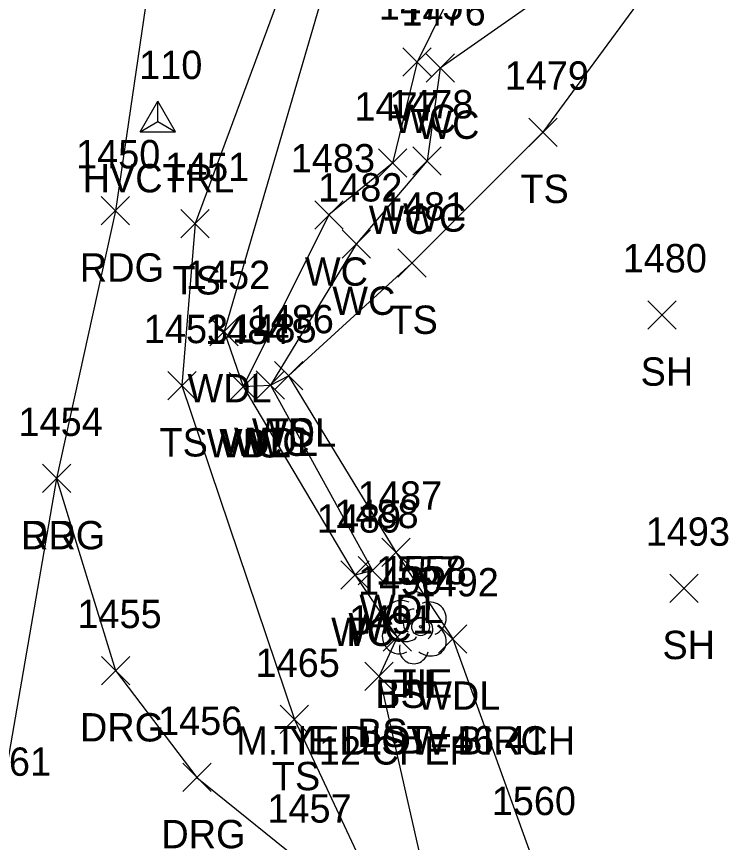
# Model space of a CAD drawing. Extents: x 1678553 to 1680768, y 787260 to 792325.
# Drawn here: x 1678687.1 to 1678737.4, y 787425.2 to 787483.5 of the extents above; entities that cross this region are included whole.
import ezdxf

# ---------------------------------------------------------------- set-up
doc = ezdxf.new("R2010")
doc.units = 0
for name, color, linetype in [('C_A', 7, 'Continuous'), ('C_C', 7, 'Continuous'), ('C_I', 7, 'Continuous'), ('CBP', 7, 'Continuous'), ('CPSM', 7, 'Continuous'), ('D_A', 7, 'Continuous'), ('D_C', 7, 'Continuous'), ('D_I', 7, 'Continuous'), ('D_TIC', 7, 'Continuous'), ('DCP', 7, 'Continuous'), ('L_A', 7, 'Continuous'), ('L_C', 7, 'Continuous'), ('L_I', 7, 'Continuous'), ('L_TIC', 7, 'Continuous'), ('LAWA', 7, 'Continuous'), ('LAWE', 7, 'Continuous'), ('LELB', 7, 'Continuous'), ('LTD', 7, 'Continuous'), ('P_A', 7, 'Continuous'), ('P_I', 7, 'Continuous'), ('P_TIC', 7, 'Continuous'), ('PEU', 7, 'Continuous'), ('R_A', 7, 'Continuous'), ('R_I', 7, 'Continuous'), ('R_TIC', 7, 'Continuous'), ('RDG', 7, 'Continuous')]:
    doc.layers.add(name, color=color, linetype=linetype)

msp = doc.modelspace()

# ---------------------------------------------------------------- linework, layer by layer
at = {"layer": 'CBP'}
for radius in [0.625, 0.0833]:
    msp.add_circle((1678715.655, 787440.466), radius, dxfattribs=at)
at = {"layer": 'CPSM'}
for p, q in [((1678695.859, 787475.405), (1678697.109, 787477.57)), ((1678698.359, 787475.405), (1678697.109, 787477.57)), ((1678697.109, 787476.127), (1678697.109, 787477.57)), ((1678695.859, 787475.405), (1678697.109, 787476.127)), ((1678697.109, 787476.127), (1678697.109, 787476.127)), ((1678697.109, 787476.127), (1678698.359, 787475.405)), ((1678695.859, 787475.405), (1678698.359, 787475.405))]:
    msp.add_line(p, q, dxfattribs=at)
at = {"layer": 'D_TIC'}
for points in [[(1678710.034, 787443.117), (1678712.034, 787445.117)], [(1678712.034, 787443.117), (1678710.034, 787445.117)], [(1678713.015, 787438.741), (1678715.015, 787440.741)], [(1678715.015, 787438.741), (1678713.015, 787440.741)]]:
    msp.add_lwpolyline(points, dxfattribs=at)
at = {"layer": 'DCP'}
msp.add_lwpolyline([(1678711.034, 787444.117), (1678714.015, 787439.741)], dxfattribs=at)
at = {"layer": 'L_TIC'}
for points in [[(1678714.409, 787479.322), (1678716.409, 787481.322)], [(1678716.409, 787479.322), (1678714.409, 787481.322)], [(1678716.048, 787478.906), (1678718.048, 787480.906)], [(1678718.048, 787478.906), (1678716.048, 787480.906)], [(1678723.288, 787474.377), (1678725.288, 787476.377)], [(1678725.288, 787474.377), (1678723.288, 787476.377)], [(1678723.288, 787474.377), (1678725.288, 787476.377)], [(1678725.288, 787474.377), (1678723.288, 787476.377)], [(1678712.685, 787472.198), (1678714.685, 787474.198)], [(1678714.685, 787472.198), (1678712.685, 787474.198)], [(1678715.12, 787472.35), (1678717.12, 787474.35)], [(1678717.12, 787472.35), (1678715.12, 787474.35)], [(1678708.183, 787468.54), (1678710.183, 787470.54)], [(1678710.183, 787468.54), (1678708.183, 787470.54)], [(1678698.74, 787467.921), (1678700.74, 787469.921)], [(1678700.74, 787467.921), (1678698.74, 787469.921)], [(1678710.115, 787466.484), (1678712.115, 787468.484)], [(1678712.115, 787466.484), (1678710.115, 787468.484)], [(1678714.047, 787465.14), (1678716.047, 787467.14)], [(1678716.047, 787465.14), (1678714.047, 787467.14)], [(1678731.695, 787461.484), (1678733.695, 787463.484)], [(1678733.695, 787461.484), (1678731.695, 787463.484)], [(1678700.786, 787460.308), (1678702.786, 787462.308)], [(1678702.786, 787460.308), (1678700.786, 787462.308)], [(1678705.335, 787457.183), (1678707.335, 787459.183)], [(1678707.335, 787457.183), (1678705.335, 787459.183)], [(1678705.335, 787457.183), (1678707.335, 787459.183)], [(1678707.335, 787457.183), (1678705.335, 787459.183)], [(1678697.818, 787456.487), (1678699.818, 787458.487)], [(1678699.818, 787456.487), (1678697.818, 787458.487)], [(1678702.147, 787456.419), (1678704.147, 787458.419)], [(1678704.147, 787456.419), (1678702.147, 787458.419)], [(1678702.147, 787456.419), (1678704.147, 787458.419)], [(1678704.147, 787456.419), (1678702.147, 787458.419)], [(1678704.06, 787456.531), (1678706.06, 787458.531)], [(1678706.06, 787456.531), (1678704.06, 787458.531)], [(1678704.06, 787456.531), (1678706.06, 787458.531)], [(1678706.06, 787456.531), (1678704.06, 787458.531)], [(1678712.921, 787444.734), (1678714.921, 787446.734)], [(1678714.921, 787444.734), (1678712.921, 787446.734)], [(1678711.259, 787443.43), (1678713.259, 787445.43)], [(1678713.259, 787443.43), (1678711.259, 787445.43)], [(1678710.034, 787443.117), (1678712.034, 787445.117)], [(1678712.034, 787443.117), (1678710.034, 787445.117)], [(1678710.034, 787443.117), (1678712.034, 787445.117)], [(1678712.034, 787443.117), (1678710.034, 787445.117)], [(1678733.235, 787442.186), (1678735.235, 787444.186)], [(1678735.235, 787442.186), (1678733.235, 787444.186)], [(1678713.015, 787438.741), (1678715.015, 787440.741)], [(1678715.015, 787438.741), (1678713.015, 787440.741)], [(1678716.921, 787438.613), (1678718.921, 787440.613)], [(1678718.921, 787438.613), (1678716.921, 787440.613)], [(1678711.733, 787435.979), (1678713.733, 787437.979)], [(1678713.733, 787435.979), (1678711.733, 787437.979)], [(1678705.749, 787432.933), (1678707.749, 787434.933)], [(1678707.749, 787432.933), (1678705.749, 787434.933)]]:
    msp.add_lwpolyline(points, dxfattribs=at)
at = {"layer": 'LAWA'}
msp.add_lwpolyline([(1678709.783, 787516.485), (1678712.28, 787497.217), (1678701.786, 787461.308), (1678703.147, 787457.419), (1678705.06, 787457.531), (1678706.335, 787458.183), (1678713.921, 787445.734), (1678717.921, 787439.613), (1678723.5, 787424.177), (1678713.912, 787402.698), (1678707.751, 787397.775), (1678697.862, 787399.447), (1678688.053, 787395.99), (1678683.78, 787387.208), (1678676.741, 787361.633), (1678672.526, 787349.762), (1678668.76, 787338.441), (1678662.119, 787319.948), (1678654.202, 787273.362)], dxfattribs=at)
at = {"layer": 'LAWE'}
for points in [[(1678722.745, 787512.606), (1678722.195, 787494.059), (1678715.409, 787480.322), (1678713.685, 787473.198), (1678709.183, 787469.54), (1678703.147, 787457.419), (1678711.034, 787444.117)], [(1678731.749, 787490.21), (1678717.048, 787479.906), (1678716.12, 787473.35), (1678711.115, 787467.484), (1678705.06, 787457.531), (1678712.259, 787444.43), (1678711.034, 787444.117)]]:
    msp.add_lwpolyline(points, dxfattribs=at)
at = {"layer": 'LELB'}
for points in [[(1678703.248, 787521.158), (1678708.077, 787504.893), (1678710.048, 787496.734), (1678699.74, 787468.921), (1678698.818, 787457.487), (1678706.749, 787433.933), (1678714.451, 787417.51), (1678705.647, 787404.222), (1678696.305, 787404.911), (1678687.529, 787400.609), (1678678.856, 787394.601), (1678669.013, 787365.188), (1678664.736, 787349.076), (1678657.46, 787321.279), (1678652.337, 787297.827), (1678647.466, 787276.322)], [(1678812.782, 787516.249), (1678783.274, 787510.424), (1678763.1, 787494.005), (1678734.556, 787489.379), (1678724.288, 787475.377)], [(1678724.288, 787475.377), (1678715.047, 787466.14), (1678706.335, 787458.183)], [(1678714.015, 787439.741), (1678712.733, 787436.979), (1678716.977, 787418.322), (1678707.935, 787402.889), (1678697.964, 787402.122), (1678688.053, 787395.99)]]:
    msp.add_lwpolyline(points, dxfattribs=at)
at = {"layer": 'LTD'}
msp.add_line((1678715.192, 787440.452), (1678715.192, 787440.452), dxfattribs=at)
msp.add_line((1678715.192, 787440.452), (1678715.192, 787440.452), dxfattribs=at)
msp.add_arc((1678715.239, 787441.886), 1.047, 335.52715, 180.95627, dxfattribs=at)
for centre, major_axis, ratio, start_param, end_param in [((1678714.401, 787441.118), (1.21, -0.512), 0.895232, 1.570796, 4.712389), ((1678716.234, 787441.035), (-1.141, -0.483), 0.949671, 1.570796, 4.712389), ((1678714.984, 787440.91), (-0.208, -0.792), 0.645439, 3.141593, 6.283185), ((1678714.109, 787439.743), (0.584, -1.042), 0.959034, 3.141593, 6.283185), ((1678715.692, 787440.285), (-0.5, 0.667), 0.989748, 3.141593, 6.283185), ((1678716.193, 787439.618), (-1.09, 0.792), 0.841452, 1.570796, 4.712389), ((1678714.734, 787439.701), (-0.625, -0.083), 0.423636, 0, 3.141593), ((1678715.193, 787438.952), (0.265, 1.061), 0.942809, 1.570796, 4.712389)]:
    msp.add_ellipse(centre, major_axis=major_axis, ratio=ratio, start_param=start_param, end_param=end_param, dxfattribs=at)
at = {"layer": 'P_TIC'}
for points in [[(1678693.118, 787468.827), (1678695.118, 787470.827)], [(1678695.118, 787468.827), (1678693.118, 787470.827)], [(1678688.971, 787449.935), (1678690.971, 787451.935)], [(1678690.971, 787449.935), (1678688.971, 787451.935)]]:
    msp.add_lwpolyline(points, dxfattribs=at)
at = {"layer": 'PEU'}
msp.add_lwpolyline([(1678701.084, 787523.46), (1678699.331, 787512.572), (1678697.82, 787495.037), (1678694.118, 787469.827), (1678689.971, 787450.935), (1678685.799, 787426.952), (1678675.551, 787395.19), (1678665.556, 787365.837), (1678662.398, 787349.046), (1678655.839, 787321.611), (1678650.229, 787298.04), (1678645.331, 787276.771)], dxfattribs=at)
at = {"layer": 'R_TIC'}
for points in [[(1678688.971, 787449.935), (1678690.971, 787451.935)], [(1678690.971, 787449.935), (1678688.971, 787451.935)], [(1678693.128, 787436.374), (1678695.128, 787438.374)], [(1678695.128, 787436.374), (1678693.128, 787438.374)], [(1678698.872, 787428.836), (1678700.872, 787430.836)], [(1678700.872, 787428.836), (1678698.872, 787430.836)]]:
    msp.add_lwpolyline(points, dxfattribs=at)
at = {"layer": 'RDG'}
msp.add_lwpolyline([(1678689.971, 787450.935), (1678694.128, 787437.374), (1678699.872, 787429.836), (1678707.534, 787423.647), (1678704.059, 787407.868), (1678691.023, 787410.562), (1678683.252, 787407.317), (1678675.551, 787395.19)], dxfattribs=at)

# ---------------------------------------------------------------- texts
at = {"layer": 'C_A'}
for s, p in [('HVCTRL', (1678691.802, 787471.127)), ('TIE', (1678713.734, 787435.466))]:
    msp.add_text(s, height=2, dxfattribs=at).set_placement(p)
at = {"layer": 'C_C'}
msp.add_text('TIE DIST=46.41', height=2, dxfattribs=at).set_placement((1678705.309, 787431.466))
at = {"layer": 'C_I'}
for s, p in [('110', (1678695.795, 787479.127)), ('1558', (1678712.962, 787443.466))]:
    msp.add_text(s, height=2, dxfattribs=at).set_placement(p)
at = {"layer": 'D_A'}
for p in [(1678710.412, 787439.117), (1678713.393, 787434.741)]:
    msp.add_text('P', height=2, dxfattribs=at).set_placement(p)
at = {"layer": 'D_C'}
msp.add_text('12 CPEP', height=2, dxfattribs=at).set_placement((1678708.48, 787430.741))
at = {"layer": 'D_I'}
for s, p in [('1489', (1678708.333, 787447.117)), ('1490', (1678711.236, 787442.741))]:
    msp.add_text(s, height=2, dxfattribs=at).set_placement(p)
at = {"layer": 'L_A'}
for s, p in [('WC', (1678713.717, 787475.322)), ('WC', (1678715.356, 787474.906)), ('TS', (1678722.697, 787470.377)), ('TS', (1678722.697, 787470.377)), ('WC', (1678711.992, 787468.198)), ('WC', (1678714.427, 787468.35)), ('WC', (1678707.49, 787464.54)), ('TS', (1678698.149, 787463.921)), ('WC', (1678709.422, 787462.484)), ('TS', (1678713.456, 787461.14)), ('SH', (1678731.183, 787457.484)), ('WDL', (1678699.203, 787456.308)), ('WDL', (1678703.752, 787453.183)), ('TS', (1678704.744, 787453.183)), ('TS', (1678697.227, 787452.487)), ('WDL', (1678700.564, 787452.419)), ('WC', (1678701.454, 787452.419)), ('WDL', (1678702.477, 787452.531)), ('WC', (1678703.367, 787452.531)), ('WDL', (1678711.338, 787440.734)), ('WC', (1678710.566, 787439.43)), ('WC', (1678709.341, 787439.117)), ('WC', (1678709.341, 787439.117)), ('SH', (1678732.723, 787438.186)), ('H', (1678714.625, 787435.452)), ('BS', (1678712.456, 787434.741)), ('WDL', (1678715.339, 787434.613)), ('BS', (1678711.174, 787431.979)), ('TS', (1678705.159, 787428.933))]:
    msp.add_text(s, height=2, dxfattribs=at).set_placement(p)
at = {"layer": 'L_C'}
msp.add_text('M. YELLOW BIRCH', height=2, dxfattribs=at).set_placement((1678702.642, 787431.452))
at = {"layer": 'L_I'}
for s, p in [('1475', (1678712.717, 787483.322)), ('1476', (1678714.301, 787482.906)), ('1479', (1678721.587, 787478.377)), ('1479', (1678721.587, 787478.377)), ('1477', (1678710.992, 787476.198)), ('1478', (1678713.428, 787476.35)), ('1483', (1678706.491, 787472.54)), ('1451', (1678697.614, 787471.921)), ('1482', (1678708.422, 787470.484)), ('1481', (1678712.921, 787469.14)), ('1480', (1678729.915, 787465.484)), ('1452', (1678699.093, 787464.308)), ('1486', (1678703.587, 787461.183)), ('1486', (1678703.587, 787461.183)), ('1453', (1678696.125, 787460.487)), ('1484', (1678700.454, 787460.419)), ('1484', (1678700.454, 787460.419)), ('1485', (1678702.367, 787460.531)), ('1485', (1678702.367, 787460.531)), ('1487', (1678711.228, 787448.734)), ('1489', (1678708.333, 787447.117)), ('1489', (1678708.333, 787447.117)), ('1488', (1678709.567, 787447.43)), ('1493', (1678731.542, 787446.186)), ('1557', (1678712.5, 787443.452)), ('1490', (1678711.236, 787442.741)), ('1492', (1678715.229, 787442.613)), ('1491', (1678710.607, 787439.979)), ('1465', (1678704.009, 787436.933)), ('1560', (1678720.673, 787427.177))]:
    msp.add_text(s, height=2, dxfattribs=at).set_placement(p)
at = {"layer": 'P_A'}
for p in [(1678691.606, 787464.827), (1678687.459, 787445.935)]:
    msp.add_text('RDG', height=2, dxfattribs=at).set_placement(p)
at = {"layer": 'P_I'}
for s, p in [('1450', (1678691.339, 787472.827)), ('1454', (1678687.278, 787453.935)), ('1461', (1678683.626, 787429.952))]:
    msp.add_text(s, height=2, dxfattribs=at).set_placement(p)
at = {"layer": 'R_A'}
for p in [(1678687.459, 787445.935), (1678691.616, 787432.374), (1678697.36, 787424.836)]:
    msp.add_text('DRG', height=2, dxfattribs=at).set_placement(p)
at = {"layer": 'R_I'}
for s, p in [('1454', (1678687.278, 787453.935)), ('1455', (1678691.435, 787440.374)), ('1456', (1678697.124, 787432.836)), ('1457', (1678704.841, 787426.647))]:
    msp.add_text(s, height=2, dxfattribs=at).set_placement(p)

doc.saveas('drawing.dxf')
